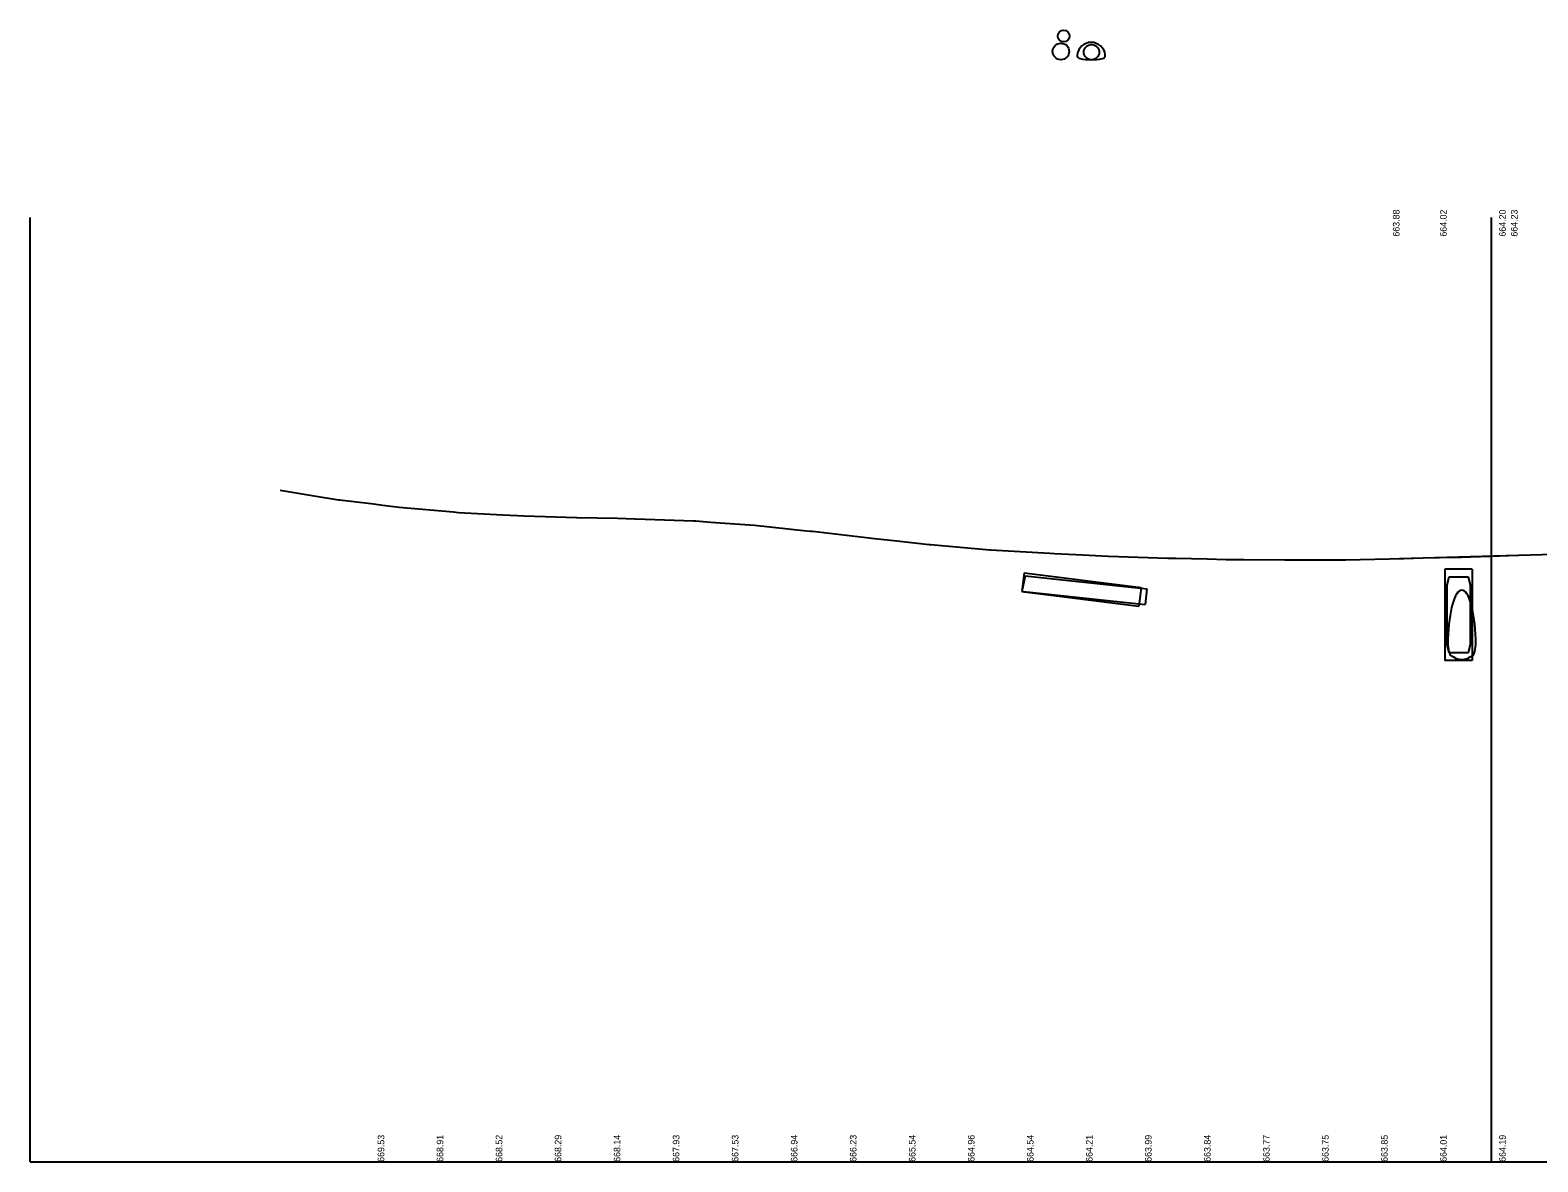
# Model space of a CAD drawing. Extents: x 2283072 to 2287933, y 586198 to 587702.
# Drawn here: x 2286711 to 2287349, y 586441 to 586920 of the extents above; entities that cross this region are included whole.
import ezdxf

# ---------------------------------------------------------------- set-up
doc = ezdxf.new("R2010")
doc.units = 0
for name, color, linetype in [('DT_X_Contour_Major', 7, 'Continuous'), ('DT_X_Spot_Elev', 7, 'Continuous'), ('DT_X_Terrain_Boundary', 7, 'Continuous'), ('DT_X_Terrain_Ground_Line', 7, 'Continuous'), ('DT_X_Triangles', 7, 'Continuous'), ('HY_X_Water_Edge', 7, 'Continuous'), ('RD_X_GR_Lt', 7, 'Continuous'), ('SV_P_Control_Cells_Set', 7, 'Continuous'), ('UT_X_Overhead_Electric', 7, 'Continuous')]:
    doc.layers.add(name, color=color, linetype=linetype)

msp = doc.modelspace()

# ---------------------------------------------------------------- linework, layer by layer
at = {"layer": 'DT_X_Contour_Major'}
for p, q in [((2287131.7, 586690.4), (2287130.71, 586682.46)), ((2287131.7, 586690.4), (2287181.33, 586684.2)), ((2287309.87, 586691.92), (2287309.87, 586653.25)), ((2287321.54, 586691.92), (2287309.87, 586691.92)), ((2287311.54, 586688.58), (2287310.71, 586685.25)), ((2287319.87, 586688.58), (2287311.54, 586688.58)), ((2287320.71, 586685.25), (2287319.87, 586688.58)), ((2287321.54, 586691.92), (2287321.54, 586653.25)), ((2287130.71, 586682.46), (2287180.34, 586676.26)), ((2287181.33, 586684.2), (2287180.34, 586676.26)), ((2287310.71, 586685.25), (2287310.71, 586659.92)), ((2287320.71, 586659.92), (2287320.71, 586685.25)), ((2287310.71, 586659.92), (2287311.54, 586656.58)), ((2287311.54, 586656.58), (2287319.87, 586656.58)), ((2287319.87, 586656.58), (2287320.71, 586659.92)), ((2287321.54, 586653.25), (2287309.87, 586653.25))]:
    msp.add_line(p, q, dxfattribs=at)
at = {"layer": 'DT_X_Spot_Elev'}
msp.add_line((2287290.71, 586696.42), (2287340.71, 586697.83), dxfattribs=at)
at = {"layer": 'DT_X_Terrain_Boundary'}
msp.add_circle((2287147.28, 586911.21), 3.5, dxfattribs=at)
at = {"layer": 'DT_X_Terrain_Ground_Line'}
for q in [(2286710.71, 586840.9), (2287932.99, 586440.9)]:
    msp.add_line((2286710.71, 586440.9), q, dxfattribs=at)
at = {"layer": 'DT_X_Triangles'}
msp.add_lwpolyline([(2286816.64, 586725.37), (2286830.19, 586723.18), (2286841.25, 586721.32), (2286841.67, 586721.25), (2286855.15, 586719.68), (2286860.13, 586719.09), (2286866.97, 586718.26), (2286867.04, 586718.25), (2286890.08, 586716.15), (2286892.12, 586715.96), (2286910.86, 586714.98), (2286917.17, 586714.64), (2286920.02, 586714.56), (2286942.08, 586713.85), (2286942.29, 586713.84), (2286959.45, 586713.49), (2286966.76, 586713.32), (2286967.12, 586713.31), (2286991.71, 586712.39), (2286992.15, 586712.38), (2286992.6, 586712.36), (2286998.87, 586711.9), (2287017.51, 586710.51), (2287038.3, 586708.38), (2287041.26, 586708.07), (2287042.08, 586708), (2287066.09, 586705.2), (2287067.02, 586705.09), (2287077.73, 586703.94), (2287091.56, 586702.42), (2287092.12, 586702.36), (2287117.15, 586700.19), (2287117.16, 586700.19), (2287117.44, 586700.16), (2287142.55, 586698.65), (2287142.59, 586698.65), (2287144.63, 586698.55), (2287156.58, 586697.95), (2287167.32, 586697.41), (2287167.42, 586697.41), (2287167.52, 586697.4), (2287192.6, 586696.66), (2287196, 586696.58), (2287209.31, 586696.28), (2287217.22, 586696.09), (2287217.25, 586696.09), (2287224.75, 586696.05), (2287242.2, 586695.95), (2287242.28, 586695.95), (2287266.88, 586695.91), (2287266.88, 586695.91), (2287267.84, 586695.94), (2287292.57, 586696.46), (2287300.71, 586696.67), (2287314.6, 586697.03), (2287314.69, 586697.03), (2287316.44, 586696.99), (2287316.5, 586696.99), (2287316.94, 586697), (2287341.07, 586697.84), (2287341.27, 586697.84), (2287366.16, 586698.52)], dxfattribs=at)
at = {"layer": 'HY_X_Water_Edge'}
msp.add_line((2287329.69, 586440.9), (2287329.69, 586840.9), dxfattribs=at)
at = {"layer": 'SV_P_Control_Cells_Set'}
for p, q in [((2287132.15, 586689.09), (2287130.71, 586682.46)), ((2287132.15, 586689.09), (2287183.73, 586683.63)), ((2287131.45, 586682.46), (2287183.03, 586677)), ((2287183.73, 586683.63), (2287183.03, 586677))]:
    msp.add_line(p, q, dxfattribs=at)
for centre, radius, start, end in [((2287160.14, 586909.04), 6, 7.64244, 172.35799), ((2287155.68, 586909.64), 1.5, 172.3558, 258.94045), ((2287160.14, 586932.46), 24.75, 258.94045, 281.05955), ((2287164.6, 586909.64), 1.5, 281.05955, 7.64244)]:
    msp.add_arc(centre, radius, start, end, dxfattribs=at)
for centre, major_axis, start_param, end_param in [((2287317.11, 586659.04), (0, 24), 4.845775, 7.720603), ((2287312.65, 586661.43), (0, 6), 1.43738, 2.948567), ((2287321.57, 586661.43), (0, 6), 3.334618, 4.845775), ((2287317.11, 586752.7), (0, 99), 2.948567, 3.334618)]:
    msp.add_ellipse(centre, major_axis=major_axis, ratio=0.25, start_param=start_param, end_param=end_param, dxfattribs=at)
at = {"layer": 'UT_X_Overhead_Electric'}
for centre, radius in [((2287148.45, 586917.73), 2.5), ((2287160.25, 586910.9), 3.25)]:
    msp.add_circle(centre, radius, dxfattribs=at)

# ---------------------------------------------------------------- texts
at = {"layer": 'RD_X_GR_Lt'}
for s, p in [('663.88', (2287290.71, 586832.78)), ('664.02', (2287310.71, 586832.78)), ('664.20', (2287335.71, 586832.78)), ('664.23', (2287340.71, 586832.78)), ('669.53', (2286860.71, 586440.9)), ('668.91', (2286885.71, 586440.9)), ('668.52', (2286910.71, 586440.9)), ('668.29', (2286935.71, 586440.9)), ('668.14', (2286960.71, 586440.9)), ('667.93', (2286985.71, 586440.9)), ('667.53', (2287010.71, 586440.9)), ('666.94', (2287035.71, 586440.9)), ('666.23', (2287060.71, 586440.9)), ('665.54', (2287085.71, 586440.9)), ('664.96', (2287110.71, 586440.9)), ('664.54', (2287135.71, 586440.9)), ('664.21', (2287160.71, 586440.9)), ('663.99', (2287185.71, 586440.9)), ('663.84', (2287210.71, 586440.9)), ('663.77', (2287235.71, 586440.9)), ('663.75', (2287260.71, 586440.9)), ('663.85', (2287285.71, 586440.9)), ('664.01', (2287310.71, 586440.9)), ('664.19', (2287335.71, 586440.9))]:
    msp.add_text(s, height=2.8, rotation=90, dxfattribs=at).set_placement(p)

doc.saveas('drawing.dxf')
